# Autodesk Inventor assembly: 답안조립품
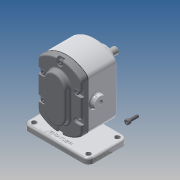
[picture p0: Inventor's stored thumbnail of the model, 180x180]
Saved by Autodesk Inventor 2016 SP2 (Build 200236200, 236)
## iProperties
Created: 2019-03
Part Number: 답안조립품
Document SubType Name: Assembly
Designer: EZ
Author: EZ
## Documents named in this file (11)
- X:\490307V1030 고영석\답안조립품.iam
- X:\490307V1030 고영석\본체1.ipt
- X:\490307V1030 고영석\베어링부시.ipt
- X:\490307V1030 고영석\메인축.ipt
- X:\490307V1030 고영석\서브축.ipt
- X:\490307V1030 고영석\키 6 x 6 x 18.ipt
- X:\490307V1030 고영석\커버.ipt
- X:\490307V1030 고영석\오일 실 16 28 7.ipt
- X:\490307V1030 고영석\스퍼기어.ipt
- X:\490307V1030 고영석\개스킷.ipt
- X:\490307V1030 고영석\볼트 M5.ipt
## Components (1 placed, 1 different names)
1. 개스킷:1
